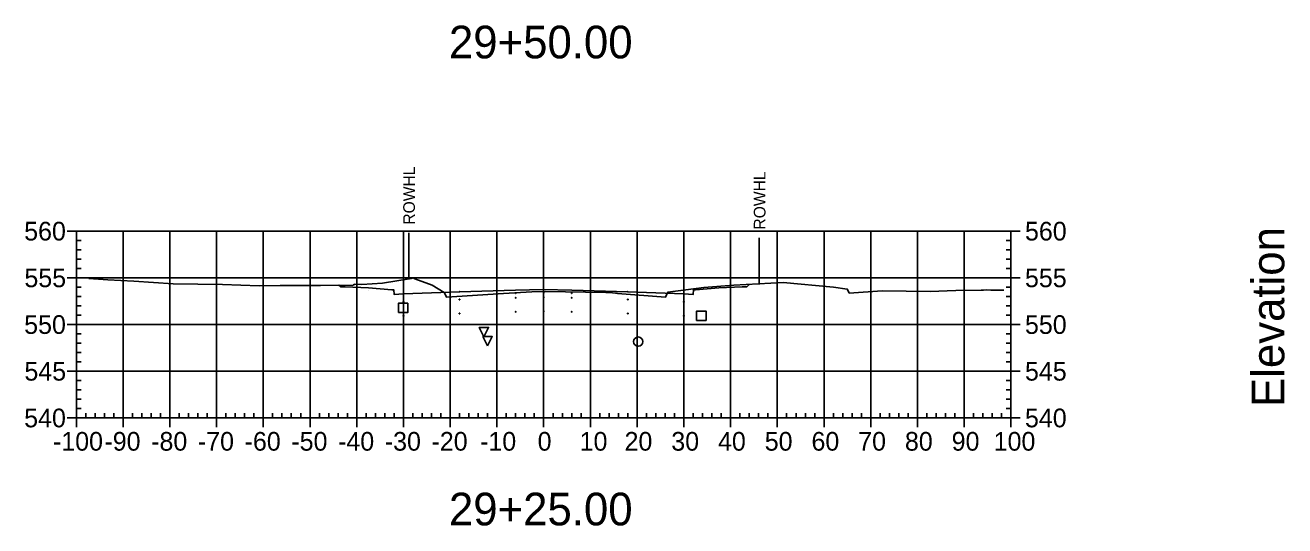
# Model space of a CAD drawing. Extents: x 708103 to 717568, y 374476 to 378707.
# Drawn here: x 710316 to 710585.6, y 377021.5 to 377128.7 of the extents above; entities that cross this region are included whole.
import ezdxf

# ---------------------------------------------------------------- set-up
doc = ezdxf.new("R2010")
doc.units = 0
for name, color, linetype in [('1', 7, 'Continuous'), ('10', 7, 'Continuous'), ('13', 7, 'Continuous'), ('14', 7, 'Continuous'), ('22', 7, 'Continuous'), ('4', 7, 'Continuous'), ('57', 7, 'Continuous'), ('60', 7, 'Continuous'), ('Existing', 7, 'Continuous'), ('XS_Right_of_Way', 7, 'Continuous')]:
    doc.layers.add(name, color=color, linetype=linetype)

msp = doc.modelspace()

# ---------------------------------------------------------------- linework, layer by layer
for points in [[(710420.93, 377071.3), (710421.03, 377071.3), (710421.03, 377071.4), (710420.93, 377071.4)], [(710420.93, 377070.3), (710421.03, 377070.3), (710421.03, 377070.4), (710420.93, 377070.4)], [(710426.93, 377071.42), (710427.03, 377071.42), (710427.03, 377071.52), (710426.93, 377071.52)], [(710426.93, 377070.42), (710427.03, 377070.42), (710427.03, 377070.52), (710426.93, 377070.52)], [(710432.93, 377071.3), (710433.03, 377071.3), (710433.03, 377071.4), (710432.93, 377071.4)], [(710432.93, 377070.3), (710433.03, 377070.3), (710433.03, 377070.4), (710432.93, 377070.4)], [(710396.93, 377069.46), (710397.03, 377069.46), (710397.03, 377069.56), (710396.93, 377069.56)], [(710408.93, 377069.94), (710409.03, 377069.94), (710409.03, 377070.04), (710408.93, 377070.04)], [(710444.93, 377069.94), (710445.03, 377069.94), (710445.03, 377070.04), (710444.93, 377070.04)], [(710456.93, 377069.46), (710457.03, 377069.46), (710457.03, 377069.56), (710456.93, 377069.56)], [(710396.93, 377066.46), (710397.03, 377066.46), (710397.03, 377066.56), (710396.93, 377066.56)], [(710408.93, 377066.94), (710409.03, 377066.94), (710409.03, 377067.04), (710408.93, 377067.04)], [(710420.93, 377067.3), (710421.03, 377067.3), (710421.03, 377067.4), (710420.93, 377067.4)], [(710426.93, 377067.42), (710427.03, 377067.42), (710427.03, 377067.52), (710426.93, 377067.52)], [(710432.93, 377067.3), (710433.03, 377067.3), (710433.03, 377067.4), (710432.93, 377067.4)], [(710444.93, 377066.94), (710445.03, 377066.94), (710445.03, 377067.04), (710444.93, 377067.04)], [(710456.93, 377066.46), (710457.03, 377066.46), (710457.03, 377066.56), (710456.93, 377066.56)]]:
    msp.add_lwpolyline(points, close=True)
at = {"layer": '1'}
for points in [[(710414.21, 377062.01), (710413.21, 377064.01), (710415.21, 377064.01)], [(710414.99, 377060.06), (710413.99, 377062.06), (710415.99, 377062.06)]]:
    msp.add_lwpolyline(points, close=True, dxfattribs=at)
at = {"layer": '10'}
msp.add_lwpolyline([(710395.88, 377067.2), (710397.88, 377067.2), (710397.88, 377069.2), (710395.88, 377069.2)], close=True, dxfattribs=at)
at = {"layer": '13'}
msp.add_circle((710447.23, 377060.97), 1, dxfattribs=at)
at = {"layer": '14'}
for points in [[(710383.2, 377073.02), (710383.2, 377073.07), (710383.2, 377073.02), (710383.15, 377073.02), (710383.2, 377073.02), (710383.2, 377072.97), (710383.2, 377073.02), (710383.25, 377073.02)], [(710470.98, 377073.23), (710470.98, 377073.28), (710470.98, 377073.23), (710470.93, 377073.23), (710470.98, 377073.23), (710470.98, 377073.18), (710470.98, 377073.23), (710471.03, 377073.23)], [(710396.98, 377071.18), (710396.98, 377071.23), (710396.98, 377071.18), (710396.93, 377071.18), (710396.98, 377071.18), (710396.98, 377071.13), (710396.98, 377071.18), (710397.03, 377071.18)], [(710408.98, 377071.66), (710408.98, 377071.71), (710408.98, 377071.66), (710408.93, 377071.66), (710408.98, 377071.66), (710408.98, 377071.61), (710408.98, 377071.66), (710409.03, 377071.66)], [(710426.98, 377072.14), (710426.98, 377072.19), (710426.98, 377072.14), (710426.93, 377072.14), (710426.98, 377072.14), (710426.98, 377072.09), (710426.98, 377072.14), (710427.03, 377072.14)], [(710444.98, 377071.66), (710444.98, 377071.71), (710444.98, 377071.66), (710444.93, 377071.66), (710444.98, 377071.66), (710444.98, 377071.61), (710444.98, 377071.66), (710445.03, 377071.66)], [(710456.98, 377071.18), (710456.98, 377071.23), (710456.98, 377071.18), (710456.93, 377071.18), (710456.98, 377071.18), (710456.98, 377071.13), (710456.98, 377071.18), (710457.03, 377071.18)]]:
    msp.add_lwpolyline(points, dxfattribs=at)
at = {"layer": '22'}
msp.add_lwpolyline([(710383.2, 377073.02), (710383.48, 377072.74), (710384.48, 377072.7), (710389.48, 377072.5), (710394.48, 377072.1), (710394.9, 377072.1), (710394.98, 377071.1), (710396.98, 377071.18), (710408.98, 377071.66), (710420.98, 377072.02), (710426.98, 377072.14), (710432.98, 377072.02), (710444.98, 377071.66), (710456.98, 377071.18), (710458.98, 377071.1), (710459.07, 377072.1), (710459.48, 377072.1), (710464.48, 377072.5), (710469.48, 377072.7), (710470.48, 377072.74), (710470.98, 377073.23)], dxfattribs=at)
at = {"layer": '4'}
msp.add_lwpolyline([(710459.72, 377065.51), (710461.72, 377065.51), (710461.72, 377067.51), (710459.72, 377067.51)], close=True, dxfattribs=at)
at = {"layer": '57'}
for p, q in [((710324.98, 377084.63), (710326.98, 377084.63)), ((710326.98, 377084.63), (710526.98, 377084.63)), ((710326.98, 377044.63), (710326.98, 377084.63)), ((710326.98, 377044.63), (710326.98, 377084.63)), ((710336.98, 377044.63), (710336.98, 377084.63)), ((710346.98, 377044.63), (710346.98, 377084.63)), ((710356.98, 377044.63), (710356.98, 377084.63)), ((710366.98, 377044.63), (710366.98, 377084.63)), ((710376.98, 377044.63), (710376.98, 377084.63)), ((710386.98, 377044.63), (710386.98, 377084.63)), ((710396.98, 377044.63), (710396.98, 377084.63)), ((710406.98, 377044.63), (710406.98, 377084.63)), ((710416.98, 377044.63), (710416.98, 377084.63)), ((710426.98, 377044.63), (710426.98, 377084.63)), ((710436.98, 377044.63), (710436.98, 377084.63)), ((710446.98, 377044.63), (710446.98, 377084.63)), ((710456.98, 377044.63), (710456.98, 377084.63)), ((710466.98, 377044.63), (710466.98, 377084.63)), ((710476.98, 377044.63), (710476.98, 377084.63)), ((710486.98, 377044.63), (710486.98, 377084.63)), ((710496.98, 377044.63), (710496.98, 377084.63)), ((710506.98, 377044.63), (710506.98, 377084.63)), ((710516.98, 377044.63), (710516.98, 377084.63)), ((710526.98, 377044.63), (710526.98, 377084.63)), ((710526.98, 377044.63), (710526.98, 377084.63)), ((710528.98, 377084.63), (710526.98, 377084.63)), ((710326.98, 377082.63), (710327.98, 377082.63)), ((710526.98, 377082.63), (710525.98, 377082.63)), ((710326.98, 377080.63), (710327.98, 377080.63)), ((710326.98, 377078.63), (710327.98, 377078.63)), ((710526.98, 377080.63), (710525.98, 377080.63)), ((710526.98, 377078.63), (710525.98, 377078.63)), ((710326.98, 377076.63), (710327.98, 377076.63)), ((710526.98, 377076.63), (710525.98, 377076.63)), ((710324.98, 377074.63), (710326.98, 377074.63)), ((710326.98, 377074.63), (710526.98, 377074.63)), ((710528.98, 377074.63), (710526.98, 377074.63)), ((710326.98, 377072.63), (710327.98, 377072.63)), ((710326.98, 377070.63), (710327.98, 377070.63)), ((710526.98, 377072.63), (710525.98, 377072.63)), ((710526.98, 377070.63), (710525.98, 377070.63)), ((710326.98, 377068.63), (710327.98, 377068.63)), ((710526.98, 377068.63), (710525.98, 377068.63)), ((710326.98, 377066.63), (710327.98, 377066.63)), ((710526.98, 377066.63), (710525.98, 377066.63)), ((710324.98, 377064.63), (710326.98, 377064.63)), ((710326.98, 377064.63), (710526.98, 377064.63)), ((710326.98, 377062.63), (710327.98, 377062.63)), ((710526.98, 377062.63), (710525.98, 377062.63)), ((710528.98, 377064.63), (710526.98, 377064.63)), ((710326.98, 377060.63), (710327.98, 377060.63)), ((710526.98, 377060.63), (710525.98, 377060.63)), ((710326.98, 377058.63), (710327.98, 377058.63)), ((710526.98, 377058.63), (710525.98, 377058.63)), ((710324.98, 377054.63), (710326.98, 377054.63)), ((710326.98, 377056.63), (710327.98, 377056.63)), ((710326.98, 377054.63), (710526.98, 377054.63)), ((710526.98, 377056.63), (710525.98, 377056.63)), ((710528.98, 377054.63), (710526.98, 377054.63)), ((710326.98, 377052.63), (710327.98, 377052.63)), ((710526.98, 377052.63), (710525.98, 377052.63)), ((710326.98, 377050.63), (710327.98, 377050.63)), ((710526.98, 377050.63), (710525.98, 377050.63)), ((710326.98, 377048.63), (710327.98, 377048.63)), ((710326.98, 377046.63), (710327.98, 377046.63)), ((710526.98, 377048.63), (710525.98, 377048.63)), ((710526.98, 377046.63), (710525.98, 377046.63)), ((710324.98, 377044.63), (710326.98, 377044.63)), ((710326.98, 377044.63), (710526.98, 377044.63)), ((710326.98, 377044.63), (710526.98, 377044.63)), ((710326.98, 377042.63), (710326.98, 377044.63)), ((710328.98, 377044.63), (710328.98, 377045.63)), ((710330.98, 377044.63), (710330.98, 377045.63)), ((710332.98, 377044.63), (710332.98, 377045.63)), ((710334.98, 377044.63), (710334.98, 377045.63)), ((710336.98, 377042.63), (710336.98, 377044.63)), ((710338.98, 377044.63), (710338.98, 377045.63)), ((710340.98, 377044.63), (710340.98, 377045.63)), ((710342.98, 377044.63), (710342.98, 377045.63)), ((710344.98, 377044.63), (710344.98, 377045.63)), ((710346.98, 377042.63), (710346.98, 377044.63)), ((710348.98, 377044.63), (710348.98, 377045.63)), ((710350.98, 377044.63), (710350.98, 377045.63)), ((710352.98, 377044.63), (710352.98, 377045.63)), ((710354.98, 377044.63), (710354.98, 377045.63)), ((710356.98, 377042.63), (710356.98, 377044.63)), ((710358.98, 377044.63), (710358.98, 377045.63)), ((710360.98, 377044.63), (710360.98, 377045.63)), ((710362.98, 377044.63), (710362.98, 377045.63)), ((710364.98, 377044.63), (710364.98, 377045.63)), ((710366.98, 377042.63), (710366.98, 377044.63)), ((710368.98, 377044.63), (710368.98, 377045.63)), ((710370.98, 377044.63), (710370.98, 377045.63)), ((710372.98, 377044.63), (710372.98, 377045.63)), ((710374.98, 377044.63), (710374.98, 377045.63)), ((710376.98, 377042.63), (710376.98, 377044.63)), ((710378.98, 377044.63), (710378.98, 377045.63)), ((710380.98, 377044.63), (710380.98, 377045.63)), ((710382.98, 377044.63), (710382.98, 377045.63)), ((710384.98, 377044.63), (710384.98, 377045.63)), ((710386.98, 377042.63), (710386.98, 377044.63)), ((710388.98, 377044.63), (710388.98, 377045.63)), ((710390.98, 377044.63), (710390.98, 377045.63)), ((710392.98, 377044.63), (710392.98, 377045.63)), ((710394.98, 377044.63), (710394.98, 377045.63)), ((710396.98, 377042.63), (710396.98, 377044.63)), ((710398.98, 377044.63), (710398.98, 377045.63)), ((710400.98, 377044.63), (710400.98, 377045.63)), ((710402.98, 377044.63), (710402.98, 377045.63)), ((710404.98, 377044.63), (710404.98, 377045.63)), ((710406.98, 377042.63), (710406.98, 377044.63)), ((710408.98, 377044.63), (710408.98, 377045.63)), ((710410.98, 377044.63), (710410.98, 377045.63)), ((710412.98, 377044.63), (710412.98, 377045.63)), ((710414.98, 377044.63), (710414.98, 377045.63)), ((710416.98, 377042.63), (710416.98, 377044.63)), ((710418.98, 377044.63), (710418.98, 377045.63)), ((710420.98, 377044.63), (710420.98, 377045.63)), ((710422.98, 377044.63), (710422.98, 377045.63)), ((710424.98, 377044.63), (710424.98, 377045.63)), ((710426.98, 377042.63), (710426.98, 377044.63)), ((710428.98, 377044.63), (710428.98, 377045.63)), ((710430.98, 377044.63), (710430.98, 377045.63)), ((710432.98, 377044.63), (710432.98, 377045.63)), ((710434.98, 377044.63), (710434.98, 377045.63)), ((710436.98, 377042.63), (710436.98, 377044.63)), ((710438.98, 377044.63), (710438.98, 377045.63)), ((710440.98, 377044.63), (710440.98, 377045.63)), ((710442.98, 377044.63), (710442.98, 377045.63)), ((710444.98, 377044.63), (710444.98, 377045.63)), ((710446.98, 377042.63), (710446.98, 377044.63)), ((710448.98, 377044.63), (710448.98, 377045.63)), ((710450.98, 377044.63), (710450.98, 377045.63)), ((710452.98, 377044.63), (710452.98, 377045.63)), ((710454.98, 377044.63), (710454.98, 377045.63)), ((710456.98, 377042.63), (710456.98, 377044.63)), ((710458.98, 377044.63), (710458.98, 377045.63)), ((710460.98, 377044.63), (710460.98, 377045.63)), ((710462.98, 377044.63), (710462.98, 377045.63)), ((710464.98, 377044.63), (710464.98, 377045.63)), ((710466.98, 377042.63), (710466.98, 377044.63)), ((710468.98, 377044.63), (710468.98, 377045.63)), ((710470.98, 377044.63), (710470.98, 377045.63)), ((710472.98, 377044.63), (710472.98, 377045.63)), ((710474.98, 377044.63), (710474.98, 377045.63)), ((710476.98, 377042.63), (710476.98, 377044.63)), ((710478.98, 377044.63), (710478.98, 377045.63)), ((710480.98, 377044.63), (710480.98, 377045.63)), ((710482.98, 377044.63), (710482.98, 377045.63)), ((710484.98, 377044.63), (710484.98, 377045.63)), ((710486.98, 377042.63), (710486.98, 377044.63)), ((710488.98, 377044.63), (710488.98, 377045.63)), ((710490.98, 377044.63), (710490.98, 377045.63)), ((710492.98, 377044.63), (710492.98, 377045.63)), ((710494.98, 377044.63), (710494.98, 377045.63)), ((710496.98, 377042.63), (710496.98, 377044.63)), ((710498.98, 377044.63), (710498.98, 377045.63)), ((710500.98, 377044.63), (710500.98, 377045.63)), ((710502.98, 377044.63), (710502.98, 377045.63)), ((710504.98, 377044.63), (710504.98, 377045.63)), ((710506.98, 377042.63), (710506.98, 377044.63)), ((710508.98, 377044.63), (710508.98, 377045.63)), ((710510.98, 377044.63), (710510.98, 377045.63)), ((710512.98, 377044.63), (710512.98, 377045.63)), ((710514.98, 377044.63), (710514.98, 377045.63)), ((710516.98, 377042.63), (710516.98, 377044.63)), ((710518.98, 377044.63), (710518.98, 377045.63)), ((710520.98, 377044.63), (710520.98, 377045.63)), ((710522.98, 377044.63), (710522.98, 377045.63)), ((710524.98, 377044.63), (710524.98, 377045.63)), ((710526.98, 377042.63), (710526.98, 377044.63)), ((710528.98, 377044.63), (710526.98, 377044.63))]:
    msp.add_line(p, q, dxfattribs=at)
at = {"layer": 'Existing'}
msp.add_lwpolyline([(710329.65, 377074.52), (710333.73, 377074.24), (710339.3, 377073.92), (710347.72, 377073.35), (710358.24, 377073.18), (710366.11, 377072.92), (710370.56, 377072.99), (710379.2, 377072.96), (710386.28, 377073.06), (710386.43, 377073.26), (710388.1, 377073.21), (710392.47, 377073.51), (710398.62, 377074.48), (710399.07, 377074.61), (710399.39, 377074.39), (710403.09, 377073.1), (710405.72, 377071.5), (710405.89, 377071.11), (710406.18, 377070.51), (710418.37, 377071.27), (710424.47, 377071.62), (710427.27, 377071.72), (710440.3, 377071.51), (710441.06, 377071.5), (710442.35, 377071.36), (710442.52, 377071.33), (710442.75, 377071.31), (710453.08, 377070.53), (710453.36, 377071.15), (710453.54, 377071.55), (710461.27, 377072.58), (710467.71, 377073.06), (710478.21, 377073.62), (710489, 377072.63), (710491.95, 377072.22), (710492.14, 377071.86), (710492.38, 377071.37), (710499.45, 377071.82), (710509.7, 377071.72), (710515.2, 377071.95), (710520.61, 377071.98), (710521.11, 377072.01), (710521.84, 377072.04), (710522.66, 377072.02), (710523.42, 377072.01), (710524.02, 377072), (710524.39, 377072), (710524.52, 377072), (710525.46, 377071.99)], dxfattribs=at)
at = {"layer": 'XS_Right_of_Way'}
for p, q in [((710398.11, 377084.26), (710398.11, 377074.26)), ((710473.13, 377083.21), (710473.13, 377073.21))]:
    msp.add_line(p, q, dxfattribs=at)

# ---------------------------------------------------------------- texts
at = {"layer": '1'}
for s, p in [('29+50.00', (710406.71, 377121.63)), ('29+25.00', (710406.71, 377021.63))]:
    msp.add_text(s, height=7, dxfattribs=at).set_placement(p)
at = {"layer": '14'}
for p in [(710384.45, 377072.65), (710384.45, 377071.98), (710389.45, 377071.78), (710464.45, 377071.78), (710469.45, 377072.65), (710469.45, 377071.98)]:
    msp.add_text('+', height=0.1, dxfattribs=at).set_placement(p)
at = {"layer": '57'}
for s, p in [('560', (710315.81, 377082.63)), ('560', (710529.98, 377082.63)), ('555', (710315.86, 377072.63)), ('555', (710529.98, 377072.63)), ('550', (710315.81, 377062.63)), ('550', (710529.98, 377062.63)), ('545', (710315.86, 377052.63)), ('545', (710529.98, 377052.63)), ('540', (710315.81, 377042.63)), ('540', (710529.98, 377042.63)), ('-100', (710321.97, 377037.63)), ('-90', (710332.98, 377037.63)), ('-80', (710342.98, 377037.63)), ('-70', (710352.98, 377037.63)), ('-60', (710362.98, 377037.63)), ('-50', (710372.98, 377037.63)), ('-40', (710382.98, 377037.63)), ('-30', (710392.98, 377037.63)), ('-20', (710402.98, 377037.63)), ('-10', (710413.37, 377037.63)), ('0', (710425.69, 377037.63)), ('10', (710434.68, 377037.63)), ('20', (710444.29, 377037.63)), ('30', (710454.29, 377037.63)), ('40', (710464.29, 377037.63)), ('50', (710474.29, 377037.63)), ('60', (710484.29, 377037.63)), ('70', (710494.29, 377037.63)), ('80', (710504.29, 377037.63)), ('90', (710514.29, 377037.63)), ('100', (710523.28, 377037.63))]:
    msp.add_text(s, height=4, dxfattribs=at).set_placement(p)
at = {"layer": '60'}
msp.add_text('Elevation', height=7, rotation=90, dxfattribs=at).set_placement((710585.48, 377046.99))
at = {"layer": 'XS_Right_of_Way'}
for p in [(710399.43, 377086.02), (710474.45, 377084.97)]:
    msp.add_text('ROWHL', height=2.5, rotation=90, dxfattribs=at).set_placement(p)

doc.saveas('drawing.dxf')
